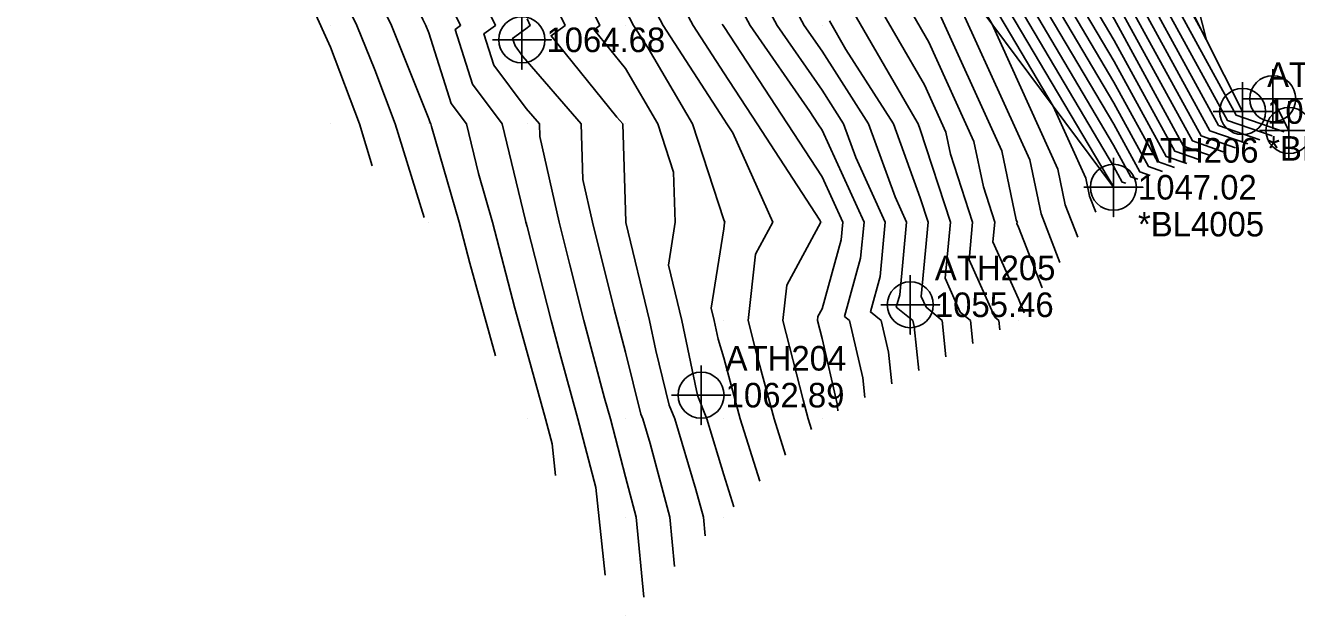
# Model space of a CAD drawing. Extents: x 1213164 to 1213550, y 766120 to 766870.
# Drawn here: x 1213299 to 1213428.3, y 766120 to 766180 of the extents above; entities that cross this region are included whole.
import ezdxf

# ---------------------------------------------------------------- set-up
doc = ezdxf.new("R2010")
doc.units = 0
for name, color, linetype in [('Default', 7, 'Continuous'), ('Exist DTM Breakline', 7, 'Continuous'), ('Exist DTM Breakline Cogo Comment', 7, 'Continuous'), ('Exist DTM Breakline Cogo Elevation', 7, 'Continuous'), ('Exist DTM Breakline Cogo Number', 7, 'Continuous'), ('Exist DTM Breakline Cogo Point CELL', 7, 'Continuous'), ('Exist DTM Crownline', 7, 'Continuous'), ('Exist DTM QL2 LIDAR Elevation Point', 7, 'Continuous'), ('Exist DTM Regular Point CELL', 7, 'Continuous'), ('Exist DTM Regular Point Cogo Elevation', 7, 'Continuous'), ('Exist DTM Regular Point Cogo Number', 7, 'Continuous'), ('Exist Roads EOP', 7, 'Continuous'), ('Exist Roads EOP Cogo Point CELL', 7, 'Continuous')]:
    doc.layers.add(name, color=color, linetype=linetype)

msp = doc.modelspace()

# ---------------------------------------------------------------- linework, layer by layer
at = {"layer": 'Default'}
for points in [[(1213427.02, 766169.17), (1213422.12, 766170.87), (1213409.81, 766193.38), (1213408.21, 766196.08), (1213407.9, 766196.6), (1213393.25, 766219.97), (1213391.95, 766221.91), (1213385.49, 766232.22), (1213385.15, 766232.72), (1213370.45, 766254.79), (1213368.43, 766257.88), (1213362.35, 766267), (1213359.46, 766271.43), (1213346.86, 766292.25), (1213345.54, 766294.24), (1213345.47, 766294.36), (1213332.57, 766313.73), (1213328.14, 766319.03), (1213322.73, 766327.12), (1213319.88, 766330.46), (1213316.46, 766335.04), (1213305.27, 766349.17), (1213304.23, 766350.49), (1213296.83, 766356.3)], [(1213424.54, 766168.36), (1213420.34, 766169.83), (1213409.79, 766189.12), (1213406.27, 766195.06), (1213405.59, 766196.21), (1213392.6, 766216.92), (1213389.56, 766221.46), (1213383.82, 766230.62), (1213383.02, 766231.83), (1213369.96, 766251.43), (1213366.3, 766257.01), (1213361.02, 766264.95), (1213356.16, 766272.38), (1213345.5, 766290), (1213343.35, 766293.24), (1213343.29, 766293.34), (1213332.54, 766309.48), (1213325.58, 766317.82), (1213321.33, 766324.16), (1213316.92, 766329.32), (1213311.63, 766336.4), (1213304.22, 766345.77), (1213303.53, 766346.64), (1213292.88, 766355.01)], [(1213425.78, 766168.77), (1213421.23, 766170.35), (1213409.8, 766191.25), (1213407.24, 766195.57), (1213406.74, 766196.41), (1213392.93, 766218.45), (1213390.76, 766221.69), (1213384.66, 766231.42), (1213384.09, 766232.28), (1213370.2, 766253.11), (1213367.37, 766257.44), (1213361.68, 766265.98), (1213357.81, 766271.9), (1213346.18, 766291.12), (1213344.45, 766293.74), (1213344.38, 766293.85), (1213332.56, 766311.61), (1213326.86, 766318.42), (1213322.03, 766325.64), (1213318.4, 766329.89), (1213314.05, 766335.72), (1213304.75, 766347.47), (1213303.88, 766348.56), (1213294.86, 766355.65)], [(1213422.06, 766167.56), (1213418.56, 766168.78), (1213409.76, 766184.86), (1213404.32, 766194.05), (1213403.27, 766195.83), (1213391.96, 766213.87), (1213387.17, 766221.02), (1213382.16, 766229.02), (1213380.88, 766230.94), (1213369.46, 766248.07), (1213364.18, 766256.14), (1213359.68, 766262.9), (1213352.86, 766273.33), (1213344.14, 766287.74), (1213341.16, 766292.24), (1213341.11, 766292.32), (1213332.51, 766305.24), (1213323.02, 766316.6), (1213319.94, 766321.2), (1213313.97, 766328.18), (1213306.81, 766337.76), (1213303.18, 766342.36), (1213302.84, 766342.79), (1213288.93, 766353.71)], [(1213423.3, 766167.96), (1213419.45, 766169.3), (1213409.77, 766186.99), (1213405.3, 766194.56), (1213404.43, 766196.02), (1213392.28, 766215.39), (1213388.37, 766221.24), (1213382.99, 766229.82), (1213381.95, 766231.39), (1213369.71, 766249.75), (1213365.24, 766256.58), (1213360.35, 766263.93), (1213354.51, 766272.85), (1213344.82, 766288.87), (1213342.26, 766292.74), (1213342.2, 766292.83), (1213332.53, 766307.36), (1213324.3, 766317.21), (1213320.64, 766322.68), (1213315.45, 766328.75), (1213309.22, 766337.08), (1213303.7, 766344.06), (1213303.19, 766344.71), (1213290.91, 766354.36)], [(1213419.58, 766166.76), (1213416.78, 766167.74), (1213409.74, 766180.61), (1213402.38, 766193.03), (1213400.96, 766195.44), (1213391.31, 766210.82), (1213384.78, 766220.58), (1213380.5, 766227.42), (1213378.74, 766230.05), (1213368.97, 766244.72), (1213362.06, 766255.27), (1213358.34, 766260.85), (1213349.57, 766274.28), (1213342.78, 766285.49), (1213338.97, 766291.24), (1213338.94, 766291.3), (1213332.48, 766300.99), (1213320.46, 766315.38), (1213318.55, 766318.23), (1213311.02, 766327.04), (1213302.39, 766338.6), (1213302.07, 766338.95), (1213301.81, 766339.2), (1213284.98, 766352.42)], [(1213420.82, 766167.16), (1213417.67, 766168.26), (1213409.75, 766182.74), (1213403.35, 766193.54), (1213402.12, 766195.63), (1213391.64, 766212.34), (1213385.98, 766220.8), (1213381.33, 766228.22), (1213379.81, 766230.49), (1213369.21, 766246.39), (1213363.12, 766255.71), (1213359.01, 766261.88), (1213351.22, 766273.8), (1213343.46, 766286.61), (1213340.07, 766291.74), (1213340.02, 766291.81), (1213332.5, 766303.12), (1213321.74, 766315.99), (1213319.25, 766319.71), (1213312.5, 766327.61), (1213304.4, 766338.44), (1213302.65, 766340.66), (1213302.49, 766340.86), (1213286.96, 766353.07)], [(1213418.34, 766166.36), (1213415.89, 766167.21), (1213409.72, 766178.48), (1213401.41, 766192.53), (1213399.8, 766195.24), (1213390.99, 766209.29), (1213383.59, 766220.36), (1213379.66, 766226.62), (1213377.67, 766229.6), (1213368.72, 766243.04), (1213360.99, 766254.84), (1213357.67, 766259.83), (1213347.92, 766274.75), (1213342.1, 766284.36), (1213337.88, 766290.74), (1213337.85, 766290.79), (1213332.47, 766298.87), (1213319.18, 766314.77), (1213317.85, 766316.75), (1213309.55, 766326.47), (1213305.45, 766331.96), (1213300.66, 766337.25), (1213296.87, 766340.88)], [(1213415.86, 766165.56), (1213414.11, 766166.17), (1213409.7, 766174.22), (1213399.47, 766191.51), (1213397.49, 766194.86), (1213390.35, 766206.24), (1213381.2, 766219.91), (1213378, 766225.02), (1213375.53, 766228.71), (1213368.22, 766239.68), (1213358.87, 766253.97), (1213356.33, 766257.78), (1213344.62, 766275.7), (1213340.74, 766282.1), (1213335.69, 766289.74), (1213335.67, 766289.77), (1213332.44, 766294.62), (1213316.62, 766313.55), (1213316.46, 766313.79), (1213314.67, 766315.89), (1213308.63, 766322.21), (1213307.01, 766323.62), (1213305.35, 766325.55), (1213297.86, 766333.83)], [(1213412.14, 766164.36), (1213411.43, 766164.6), (1213409.66, 766167.84), (1213396.55, 766189.99), (1213394.01, 766194.27), (1213389.38, 766201.66), (1213377.62, 766219.25), (1213375.5, 766222.62), (1213372.32, 766227.38), (1213367.48, 766234.65), (1213355.68, 766252.67), (1213354.33, 766254.71), (1213339.67, 766277.13), (1213338.7, 766278.72), (1213332.4, 766288.24), (1213332.4, 766288.24), (1213332.39, 766288.26), (1213332.33, 766288.33), (1213318.13, 766301.73), (1213313.49, 766307.46), (1213311.09, 766310.59), (1213309.78, 766311.96), (1213303.72, 766317.22), (1213297.53, 766324.43)], [(1213406.02, 766158.46), (1213404.75, 766161.75), (1213403.99, 766165.4), (1213397.26, 766180.19), (1213392.67, 766187.96), (1213389.39, 766193.5), (1213388.09, 766195.56), (1213372.84, 766218.36), (1213372.18, 766219.42), (1213368.04, 766225.6), (1213366.49, 766227.93), (1213355.2, 766245.18), (1213351.86, 766249.5), (1213351.15, 766250.37), (1213350.44, 766251.02), (1213338.92, 766265.16), (1213334.51, 766269.9), (1213332.06, 766271.95), (1213324.14, 766279.45), (1213322.27, 766281.51), (1213320, 766284.17), (1213315.66, 766290), (1213310, 766297.41)], [(1213410.9, 766163.96), (1213410.54, 766164.08), (1213409.65, 766165.71), (1213395.58, 766189.48), (1213392.86, 766194.08), (1213389.06, 766200.14), (1213376.42, 766219.03), (1213374.67, 766221.82), (1213371.25, 766226.93), (1213367.23, 766232.97), (1213354.62, 766252.24), (1213353.66, 766253.68), (1213338.05, 766277.55), (1213338.03, 766277.58), (1213338.02, 766277.59), (1213338.02, 766277.59), (1213338.01, 766277.6), (1213329.88, 766286.57), (1213327.91, 766288.87), (1213318.81, 766297.46)], [(1213413.38, 766164.76), (1213412.32, 766165.13), (1213409.68, 766169.97), (1213397.52, 766190.49), (1213395.17, 766194.47), (1213389.7, 766203.19), (1213378.81, 766219.47), (1213376.34, 766223.42), (1213373.39, 766227.82), (1213367.73, 766236.32), (1213356.74, 766253.1), (1213355, 766255.73), (1213341.32, 766276.65), (1213339.38, 766279.85), (1213333.5, 766288.74), (1213333.49, 766288.75), (1213332.41, 766290.38), (1213326.45, 766297.51)], [(1213417.1, 766165.96), (1213415, 766166.69), (1213409.71, 766176.35), (1213400.44, 766192.02), (1213398.64, 766195.05), (1213390.67, 766207.77), (1213382.39, 766220.14), (1213378.83, 766225.82), (1213376.6, 766229.16), (1213368.47, 766241.36), (1213359.93, 766254.41), (1213357, 766258.81), (1213346.27, 766275.23), (1213341.42, 766283.23), (1213336.78, 766290.24), (1213336.76, 766290.28), (1213332.45, 766296.75)], [(1213407.84, 766161.03), (1213407.21, 766162.66), (1213406.84, 766164.47), (1213403.5, 766171.81), (1213393.64, 766188.46), (1213390.54, 766193.69), (1213388.41, 766197.09), (1213374.03, 766218.59), (1213373.01, 766220.22), (1213369.11, 766226.04), (1213366.74, 766229.61), (1213352.5, 766251.37), (1213352.32, 766251.63), (1213349.48, 766255.97), (1213338.62, 766269.3), (1213335.68, 766272.46), (1213334.04, 766273.83), (1213328.77, 766278.83), (1213324.81, 766283.2), (1213320, 766288.82), (1213319.12, 766290), (1213316.29, 766293.71)], [(1213409.66, 766163.56), (1213409.65, 766163.56), (1213409.64, 766163.58), (1213394.61, 766188.97), (1213391.7, 766193.88), (1213388.73, 766198.61), (1213375.23, 766218.81), (1213373.84, 766221.02), (1213370.18, 766226.49), (1213366.98, 766231.29), (1213353.56, 766251.8), (1213352.99, 766252.66), (1213343.77, 766266.76), (1213338.32, 766273.44), (1213336.85, 766275.02), (1213336.03, 766275.71), (1213333.39, 766278.22), (1213327.35, 766284.88), (1213323.38, 766289.52), (1213319.49, 766293.19)], [(1213414.62, 766165.16), (1213413.22, 766165.65), (1213409.69, 766172.1), (1213398.5, 766191), (1213396.33, 766194.66), (1213390.02, 766204.72), (1213380.01, 766219.69), (1213377.17, 766224.22), (1213374.46, 766228.27), (1213367.97, 766238), (1213357.81, 766253.54), (1213355.67, 766256.76), (1213342.97, 766276.18), (1213340.06, 766280.98), (1213334.59, 766289.24), (1213334.58, 766289.26), (1213332.42, 766292.5)], [(1213339.53, 766160.47), (1213336.58, 766170), (1213334.5, 766175.5), (1213332.7, 766180), (1213330, 766185.46), (1213327.6, 766190), (1213325.22, 766194.78), (1213322.53, 766200), (1213320, 766204.47), (1213316.56, 766210), (1213310, 766217.58), (1213307.97, 766220), (1213300, 766228.84), (1213298.91, 766230), (1213290, 766238.95), (1213281.79, 766246.43)], [(1213346.79, 766146.42), (1213344.17, 766155.83), (1213343.09, 766160), (1213340.28, 766169.72), (1213340.21, 766170), (1213340.13, 766170.11), (1213340, 766170.51), (1213336.2, 766180), (1213332.48, 766187.52), (1213331.27, 766190), (1213330, 766192.5), (1213326.13, 766200), (1213321.09, 766208.91), (1213320.47, 766210), (1213320.31, 766210.14), (1213320, 766210.8), (1213312.38, 766220), (1213310, 766222.2), (1213303.03, 766230), (1213300, 766232.77), (1213292.8, 766240)], [(1213352.88, 766134.24), (1213352.54, 766137.46), (1213351.88, 766140), (1213350, 766146.76), (1213348.75, 766151.25), (1213346.49, 766160), (1213345.06, 766164.94), (1213343.83, 766170), (1213342.29, 766172.07), (1213340, 766179.24), (1213339.7, 766180), (1213339.4, 766180.6), (1213334.81, 766190), (1213330, 766199.48), (1213329.73, 766200), (1213329.38, 766200.62), (1213324.07, 766210), (1213322.68, 766211.19), (1213320, 766216.88), (1213317.41, 766220), (1213310, 766226.86), (1213307.2, 766230), (1213300, 766236.58), (1213296.59, 766240)], [(1213334.26, 766165.74), (1213332.94, 766170), (1213330, 766177.79), (1213328.18, 766181.82), (1213323.86, 766190), (1213320, 766197.76), (1213318.89, 766200), (1213316.88, 766203.12), (1213312.6, 766210), (1213310, 766213.01), (1213304.13, 766220), (1213300, 766224.57), (1213294.91, 766230), (1213290, 766234.93), (1213285.48, 766239.05)], [(1213415.93, 766191), (1213419.06, 766178.63), (1213409.82, 766195.51)], [(1213387.11, 766143.55), (1213386.78, 766146.78), (1213386.02, 766150), (1213384.92, 766150.88), (1213385.91, 766154.47), (1213386.44, 766160), (1213383.44, 766166.56), (1213382.19, 766170), (1213380, 766173.43), (1213375.45, 766180), (1213370.07, 766189.93)], [(1213368.11, 766128.11), (1213367.94, 766130), (1213367.18, 766132.82), (1213365.03, 766140), (1213364.46, 766141.4), (1213363.09, 766146.95), (1213362.46, 766150), (1213360.04, 766159.96), (1213360.04, 766160), (1213360, 766161.2), (1213359.74, 766170), (1213359.14, 766170.69), (1213352.44, 766178.95), (1213353.87, 766180), (1213350, 766187.82)], [(1213357.94, 766124.12), (1213356.99, 766133.01), (1213355.18, 766140), (1213353.32, 766146.68), (1213352.44, 766150), (1213350, 766159.57), (1213349.89, 766160), (1213349.84, 766160.16), (1213347.45, 766170), (1213344.45, 766174.02), (1213342.67, 766179.59), (1213343.24, 766180), (1213340, 766186.62)], [(1213376.3, 766136.3), (1213375.12, 766140), (1213373.34, 766146.66), (1213372.49, 766150), (1213373.24, 766156.76), (1213374.99, 766160), (1213370.92, 766169.08), (1213370.32, 766170), (1213370, 766170.49), (1213363.86, 766180), (1213360, 766187.26)], [(1213378.92, 766138.92), (1213378.58, 766140), (1213378.07, 766141.93), (1213376.01, 766150), (1213376.41, 766153.59), (1213379.88, 766160), (1213379.79, 766160.21), (1213373.41, 766170), (1213370, 766175.19), (1213366.9, 766180), (1213363.38, 766186.62)], [(1213404.2, 766155.9), (1213402.29, 766160.84), (1213401.15, 766166.34), (1213391.76, 766186.97)], [(1213361.86, 766121.86), (1213361.11, 766130), (1213360, 766134.12), (1213358.48, 766140), (1213357.89, 766142.11), (1213355.79, 766150), (1213354.35, 766155.65), (1213353.27, 766160), (1213351.3, 766168.7), (1213351.26, 766170), (1213349.9, 766171.57), (1213346.61, 766175.97), (1213345.6, 766179.14), (1213346.78, 766180), (1213343.71, 766186.29)], [(1213371.04, 766131.04), (1213370, 766134.32), (1213368.3, 766140), (1213367.37, 766142.3), (1213367.23, 766142.87), (1213365.75, 766150), (1213364.38, 766155.62), (1213365.08, 766160), (1213364.9, 766165.1), (1213363.31, 766170), (1213360, 766175.63), (1213356.81, 766179.56), (1213357.41, 766180), (1213354.88, 766185.12)], [(1213384.37, 766142.18), (1213384.16, 766144.16), (1213382.8, 766150), (1213382.29, 766150.41), (1213383.93, 766156.33), (1213384.28, 766160), (1213380, 766169.35), (1213379.57, 766170), (1213378.76, 766171.24), (1213372.69, 766180), (1213370, 766184.98)], [(1213389.85, 766144.93), (1213389.39, 766149.39), (1213389.25, 766150), (1213387.55, 766151.35), (1213387.9, 766152.61), (1213388.61, 766160), (1213387.43, 766162.57), (1213384.72, 766170), (1213380, 766177.4), (1213378.2, 766180), (1213376.08, 766183.92)], [(1213400.55, 766150.78), (1213400, 766152.21), (1213397.39, 766158.01), (1213397.58, 766160), (1213396.42, 766163.58), (1213395.46, 766168.21), (1213390.86, 766178.31), (1213387.23, 766184.59)], [(1213398.09, 766149.04), (1213397.99, 766150), (1213397.57, 766150.35), (1213394.96, 766156.16), (1213395.32, 766160), (1213393.07, 766166.93), (1213392.61, 766169.14), (1213390.41, 766173.98), (1213385.07, 766183.22)], [(1213402.38, 766153.34), (1213400, 766159.48), (1213399.83, 766159.87), (1213399.84, 766160), (1213399.76, 766160.24), (1213398.3, 766167.27), (1213391.31, 766182.64)], [(1213373.67, 766133.67), (1213371.66, 766140), (1213370, 766146.22), (1213369.43, 766148.12), (1213369.04, 766150), (1213368.73, 766151.27), (1213370, 766159.31), (1213370.07, 766159.93), (1213370.11, 766160), (1213370, 766160.24), (1213366.84, 766170), (1213362.31, 766177.69), (1213360.82, 766180), (1213360, 766181.54)], [(1213395.34, 766147.67), (1213395.1, 766150), (1213394.07, 766150.86), (1213392.53, 766154.31), (1213393.06, 766160), (1213390, 766169.43), (1213389.79, 766170), (1213389.43, 766170.57), (1213382.91, 766181.85)], [(1213364.98, 766124.98), (1213364.52, 766130), (1213362.51, 766137.49), (1213361.76, 766140), (1213361.56, 766140.49), (1213360, 766146.79), (1213359.15, 766150), (1213358.86, 766151.14), (1213356.65, 766160), (1213355.67, 766164.33), (1213355.5, 766170), (1213349.57, 766176.86), (1213348.78, 766177.92), (1213348.53, 766178.69), (1213349.88, 766179.67), (1213350.33, 766180), (1213350, 766180.66)], [(1213381.62, 766140.81), (1213381.54, 766141.54), (1213380, 766148.17), (1213379.53, 766150), (1213379.58, 766150.42), (1213380, 766151.19), (1213381.94, 766158.19), (1213382.11, 766160), (1213380, 766164.62), (1213376.49, 766170), (1213370, 766179.9), (1213369.93, 766180), (1213369.86, 766180.14)], [(1213392.6, 766146.3), (1213392.21, 766150), (1213390.58, 766151.37), (1213390.09, 766152.45), (1213390.8, 766160), (1213390, 766162.47), (1213387.26, 766170), (1213382.43, 766177.57), (1213380.75, 766180.48)]]:
    msp.add_lwpolyline(points, dxfattribs=at)
at = {"layer": 'Exist DTM Breakline'}
for points in [[(1213422.78, 766171.25), (1213409.83, 766196.93), (1213386.66, 766233.35), (1213364.33, 766270.03), (1213348.91, 766295.97), (1213348.91, 766295.97), (1213325.28, 766332.54), (1213305.81, 766359.24), (1213281.25, 766381.47), (1213256.99, 766395.59), (1213227.81, 766408.56), (1213197.43, 766416.07)], [(1213409.64, 766163.55), (1213387.59, 766193.2), (1213366.02, 766224.76), (1213332.39, 766288.23), (1213308.21, 766325.96), (1213302.17, 766339.08)]]:
    msp.add_lwpolyline(points, dxfattribs=at)
at = {"layer": 'Exist DTM Breakline Cogo Point CELL'}
for points in [[(1213422.78, 766174.25), (1213422.78, 766168.25), (1213422.78, 766171.25), (1213425.78, 766171.25), (1213419.78, 766171.25)], [(1213409.64, 766166.55), (1213409.64, 766160.55), (1213409.64, 766163.55), (1213412.64, 766163.55), (1213406.64, 766163.55)]]:
    msp.add_lwpolyline(points, dxfattribs=at)
for centre in [(1213422.78, 766171.25), (1213409.64, 766163.55)]:
    msp.add_circle(centre, 2.34, dxfattribs=at)
at = {"layer": 'Exist DTM Crownline'}
msp.add_spline([(1213434.71, 766176.25), (1213419.05, 766204.58), (1213408.83, 766222.6)], degree=3, dxfattribs=at)
at = {"layer": 'Exist DTM QL2 LIDAR Elevation Point'}
for p, q in [((1213330, 766180), (1213330, 766180)), ((1213340, 766180), (1213340, 766180)), ((1213350, 766180), (1213350, 766180)), ((1213360, 766180), (1213360, 766180)), ((1213370, 766180), (1213370, 766180)), ((1213380, 766180), (1213380, 766180)), ((1213330, 766170), (1213330, 766170)), ((1213340, 766170), (1213340, 766170)), ((1213350, 766170), (1213350, 766170)), ((1213360, 766170), (1213360, 766170)), ((1213370, 766170), (1213370, 766170)), ((1213380, 766170), (1213380, 766170)), ((1213390, 766170), (1213390, 766170)), ((1213340, 766160), (1213340, 766160)), ((1213350, 766160), (1213350, 766160)), ((1213360, 766160), (1213360, 766160)), ((1213370, 766160), (1213370, 766160)), ((1213380, 766160), (1213380, 766160)), ((1213390, 766160), (1213390, 766160)), ((1213400, 766160), (1213400, 766160)), ((1213350, 766150), (1213350, 766150)), ((1213360, 766150), (1213360, 766150)), ((1213370, 766150), (1213370, 766150)), ((1213380, 766150), (1213380, 766150)), ((1213390, 766150), (1213390, 766150)), ((1213400, 766150), (1213400, 766150)), ((1213350, 766140), (1213350, 766140)), ((1213360, 766140), (1213360, 766140)), ((1213370, 766140), (1213370, 766140)), ((1213380, 766140), (1213380, 766140)), ((1213360, 766130), (1213360, 766130)), ((1213370, 766130), (1213370, 766130)), ((1213360, 766120), (1213360, 766120))]:
    msp.add_line(p, q, dxfattribs=at)
at = {"layer": 'Exist DTM Regular Point CELL'}
for points in [[(1213349.47, 766181.54), (1213349.47, 766175.54), (1213349.47, 766178.54), (1213352.47, 766178.54), (1213346.47, 766178.54)], [(1213388.98, 766154.6), (1213388.98, 766148.6), (1213388.98, 766151.6), (1213391.98, 766151.6), (1213385.98, 766151.6)], [(1213367.7, 766145.41), (1213367.7, 766139.41), (1213367.7, 766142.41), (1213370.7, 766142.41), (1213364.7, 766142.41)]]:
    msp.add_lwpolyline(points, dxfattribs=at)
for centre in [(1213349.47, 766178.54), (1213388.98, 766151.6), (1213367.7, 766142.41)]:
    msp.add_circle(centre, 2.34, dxfattribs=at)
at = {"layer": 'Exist Roads EOP'}
msp.add_line((1213425.85, 766172.55), (1213427.5, 766169.32), dxfattribs=at)
at = {"layer": 'Exist Roads EOP Cogo Point CELL'}
for points in [[(1213425.85, 766175.55), (1213425.85, 766169.55), (1213425.85, 766172.55), (1213428.85, 766172.55), (1213422.85, 766172.55)], [(1213427.5, 766172.32), (1213427.5, 766166.32), (1213427.5, 766169.32), (1213430.5, 766169.32), (1213424.5, 766169.32)]]:
    msp.add_lwpolyline(points, dxfattribs=at)
for centre in [(1213425.85, 766172.55), (1213427.5, 766169.32)]:
    msp.add_circle(centre, 2.34, dxfattribs=at)

# ---------------------------------------------------------------- texts
at = {"layer": 'Exist DTM Breakline Cogo Comment'}
for s, p in [('*BL4005A', (1213425.28, 766166.25)), ('*BL4005', (1213412.14, 766158.55))]:
    msp.add_text(s, height=2.5, dxfattribs=at).set_placement(p)
at = {"layer": 'Exist DTM Breakline Cogo Elevation'}
for s, p in [('1032.27', (1213425.28, 766170)), ('1047.02', (1213412.14, 766162.3))]:
    msp.add_text(s, height=2.5, dxfattribs=at).set_placement(p)
at = {"layer": 'Exist DTM Breakline Cogo Number'}
for s, p in [('ATH207', (1213425.28, 766173.75)), ('ATH206', (1213412.14, 766166.05))]:
    msp.add_text(s, height=2.5, dxfattribs=at).set_placement(p)
at = {"layer": 'Exist DTM Regular Point Cogo Elevation'}
for s, p in [('1064.68', (1213351.97, 766177.29)), ('1055.46', (1213391.48, 766150.35)), ('1062.89', (1213370.2, 766141.16))]:
    msp.add_text(s, height=2.5, dxfattribs=at).set_placement(p)
at = {"layer": 'Exist DTM Regular Point Cogo Number'}
for s, p in [('ATH205', (1213391.48, 766154.1)), ('ATH204', (1213370.2, 766144.91))]:
    msp.add_text(s, height=2.5, dxfattribs=at).set_placement(p)

doc.saveas('drawing.dxf')
